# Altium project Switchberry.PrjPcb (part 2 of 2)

## Sheet 09-Switch_Power_Filters.SchDoc
size B; SheetNumber: 9; SheetTotal: 11
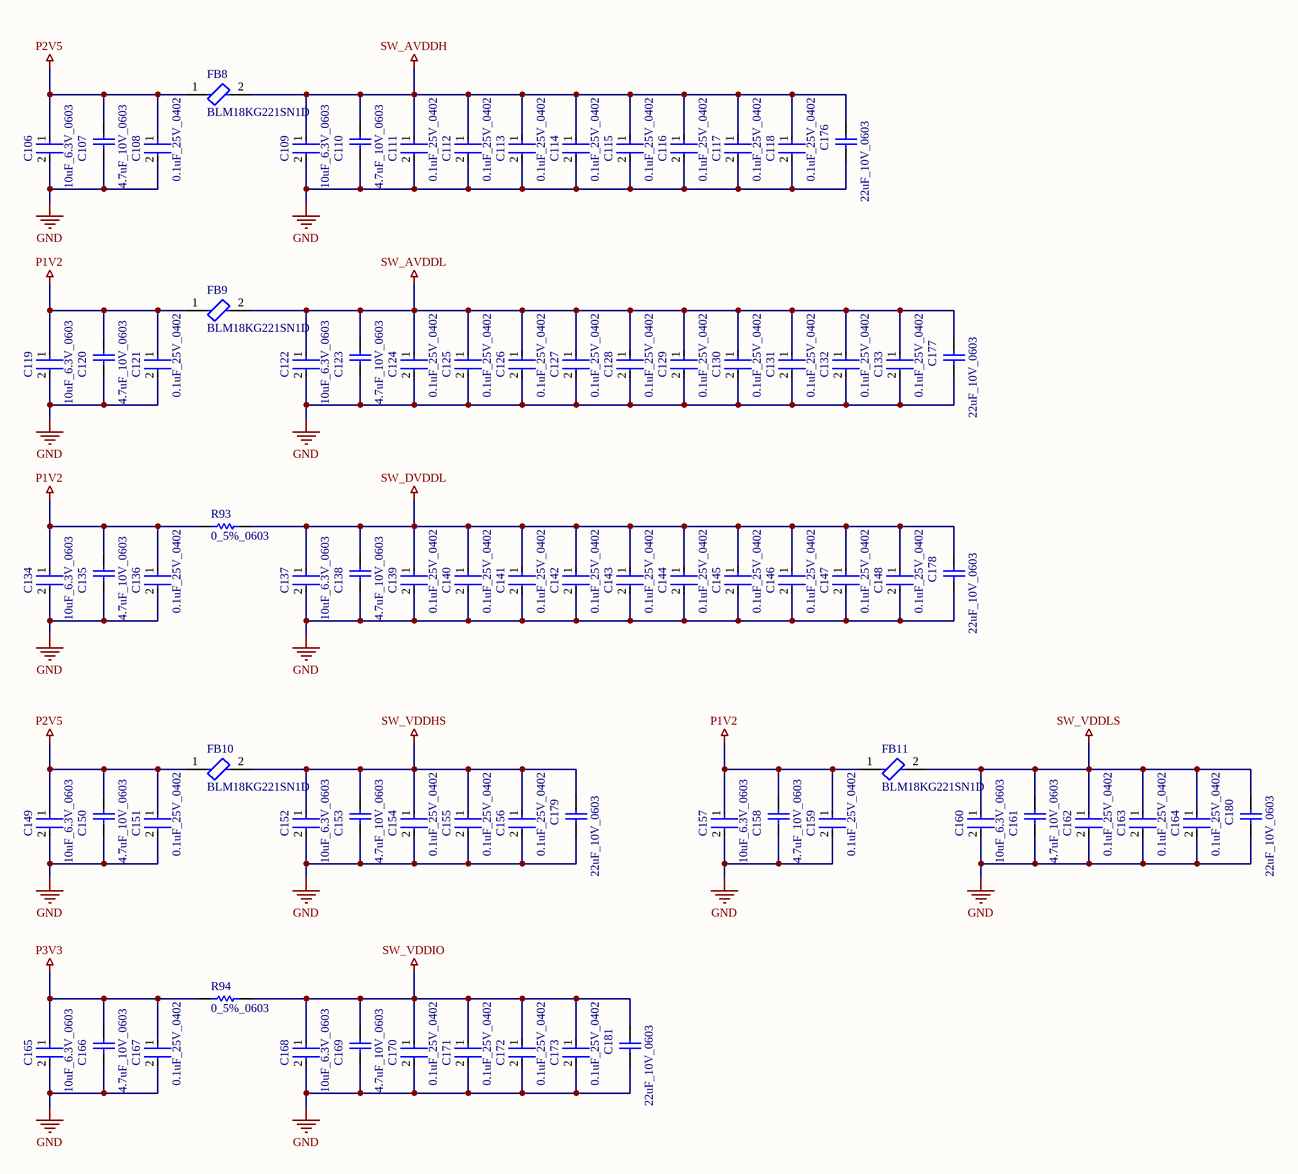
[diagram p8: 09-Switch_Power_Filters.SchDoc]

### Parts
C106  10uF_6.3V_0603  [FP-C0603C106M9PACTU-MFG]
C107  4.7uF_10V_0603  [CAPC1608X87X35NL15T15]
C108  0.1uF_25V_0402  [FP-0402-L_1_0_1-W_0_5_0_1-IPC_C]
C109  10uF_6.3V_0603  [FP-C0603C106M9PACTU-MFG]
C110  4.7uF_10V_0603  [CAPC1608X87X35NL15T15]
C111  0.1uF_25V_0402  [FP-0402-L_1_0_1-W_0_5_0_1-IPC_C]
C112  0.1uF_25V_0402  [FP-0402-L_1_0_1-W_0_5_0_1-IPC_C]
C113  0.1uF_25V_0402  [FP-0402-L_1_0_1-W_0_5_0_1-IPC_C]
C114  0.1uF_25V_0402  [FP-0402-L_1_0_1-W_0_5_0_1-IPC_C]
C115  0.1uF_25V_0402  [FP-0402-L_1_0_1-W_0_5_0_1-IPC_C]
C116  0.1uF_25V_0402  [FP-0402-L_1_0_1-W_0_5_0_1-IPC_C]
C117  0.1uF_25V_0402  [FP-0402-L_1_0_1-W_0_5_0_1-IPC_C]
C118  0.1uF_25V_0402  [FP-0402-L_1_0_1-W_0_5_0_1-IPC_C]
C119  10uF_6.3V_0603  [FP-C0603C106M9PACTU-MFG]
C120  4.7uF_10V_0603  [CAPC1608X87X35NL15T15]
C121  0.1uF_25V_0402  [FP-0402-L_1_0_1-W_0_5_0_1-IPC_C]
C122  10uF_6.3V_0603  [FP-C0603C106M9PACTU-MFG]
C123  4.7uF_10V_0603  [CAPC1608X87X35NL15T15]
C124  0.1uF_25V_0402  [FP-0402-L_1_0_1-W_0_5_0_1-IPC_C]
C125  0.1uF_25V_0402  [FP-0402-L_1_0_1-W_0_5_0_1-IPC_C]
C126  0.1uF_25V_0402  [FP-0402-L_1_0_1-W_0_5_0_1-IPC_C]
C127  0.1uF_25V_0402  [FP-0402-L_1_0_1-W_0_5_0_1-IPC_C]
C128  0.1uF_25V_0402  [FP-0402-L_1_0_1-W_0_5_0_1-IPC_C]
C129  0.1uF_25V_0402  [FP-0402-L_1_0_1-W_0_5_0_1-IPC_C]
C130  0.1uF_25V_0402  [FP-0402-L_1_0_1-W_0_5_0_1-IPC_C]
C131  0.1uF_25V_0402  [FP-0402-L_1_0_1-W_0_5_0_1-IPC_C]
C132  0.1uF_25V_0402  [FP-0402-L_1_0_1-W_0_5_0_1-IPC_C]
C133  0.1uF_25V_0402  [FP-0402-L_1_0_1-W_0_5_0_1-IPC_C]
C134  10uF_6.3V_0603  [FP-C0603C106M9PACTU-MFG]
C135  4.7uF_10V_0603  [CAPC1608X87X35NL15T15]
C136  0.1uF_25V_0402  [FP-0402-L_1_0_1-W_0_5_0_1-IPC_C]
C137  10uF_6.3V_0603  [FP-C0603C106M9PACTU-MFG]
C138  4.7uF_10V_0603  [CAPC1608X87X35NL15T15]
C139  0.1uF_25V_0402  [FP-0402-L_1_0_1-W_0_5_0_1-IPC_C]
C140  0.1uF_25V_0402  [FP-0402-L_1_0_1-W_0_5_0_1-IPC_C]
C141  0.1uF_25V_0402  [FP-0402-L_1_0_1-W_0_5_0_1-IPC_C]
C142  0.1uF_25V_0402  [FP-0402-L_1_0_1-W_0_5_0_1-IPC_C]
C143  0.1uF_25V_0402  [FP-0402-L_1_0_1-W_0_5_0_1-IPC_C]
C144  0.1uF_25V_0402  [FP-0402-L_1_0_1-W_0_5_0_1-IPC_C]
C145  0.1uF_25V_0402  [FP-0402-L_1_0_1-W_0_5_0_1-IPC_C]
C146  0.1uF_25V_0402  [FP-0402-L_1_0_1-W_0_5_0_1-IPC_C]
C147  0.1uF_25V_0402  [FP-0402-L_1_0_1-W_0_5_0_1-IPC_C]
C148  0.1uF_25V_0402  [FP-0402-L_1_0_1-W_0_5_0_1-IPC_C]
C149  10uF_6.3V_0603  [FP-C0603C106M9PACTU-MFG]
C150  4.7uF_10V_0603  [CAPC1608X87X35NL15T15]
C151  0.1uF_25V_0402  [FP-0402-L_1_0_1-W_0_5_0_1-IPC_C]
C152  10uF_6.3V_0603  [FP-C0603C106M9PACTU-MFG]
C153  4.7uF_10V_0603  [CAPC1608X87X35NL15T15]
C154  0.1uF_25V_0402  [FP-0402-L_1_0_1-W_0_5_0_1-IPC_C]
C155  0.1uF_25V_0402  [FP-0402-L_1_0_1-W_0_5_0_1-IPC_C]
C156  0.1uF_25V_0402  [FP-0402-L_1_0_1-W_0_5_0_1-IPC_C]
C157  10uF_6.3V_0603  [FP-C0603C106M9PACTU-MFG]
C158  4.7uF_10V_0603  [CAPC1608X87X35NL15T15]
C159  0.1uF_25V_0402  [FP-0402-L_1_0_1-W_0_5_0_1-IPC_C]
C160  10uF_6.3V_0603  [FP-C0603C106M9PACTU-MFG]
C161  4.7uF_10V_0603  [CAPC1608X87X35NL15T15]
C162  0.1uF_25V_0402  [FP-0402-L_1_0_1-W_0_5_0_1-IPC_C]
C163  0.1uF_25V_0402  [FP-0402-L_1_0_1-W_0_5_0_1-IPC_C]
C164  0.1uF_25V_0402  [FP-0402-L_1_0_1-W_0_5_0_1-IPC_C]
C165  10uF_6.3V_0603  [FP-C0603C106M9PACTU-MFG]
C166  4.7uF_10V_0603  [CAPC1608X87X35NL15T15]
C167  0.1uF_25V_0402  [FP-0402-L_1_0_1-W_0_5_0_1-IPC_C]
C168  10uF_6.3V_0603  [FP-C0603C106M9PACTU-MFG]
C169  4.7uF_10V_0603  [CAPC1608X87X35NL15T15]
C170  0.1uF_25V_0402  [FP-0402-L_1_0_1-W_0_5_0_1-IPC_C]
C171  0.1uF_25V_0402  [FP-0402-L_1_0_1-W_0_5_0_1-IPC_C]
C172  0.1uF_25V_0402  [FP-0402-L_1_0_1-W_0_5_0_1-IPC_C]
C173  0.1uF_25V_0402  [FP-0402-L_1_0_1-W_0_5_0_1-IPC_C]
C176  22uF_10V_0603  [CAPC1608X100X20ML10]
C177  22uF_10V_0603  [CAPC1608X100X20ML10]
C178  22uF_10V_0603  [CAPC1608X100X20ML10]
C179  22uF_10V_0603  [CAPC1608X100X20ML10]
C180  22uF_10V_0603  [CAPC1608X100X20ML10]
C181  22uF_10V_0603  [CAPC1608X100X20ML10]
FB8  BLM18KG221SN1D  [FP-BLM18-0_15-t0_8-IPC_B]
FB9  BLM18KG221SN1D  [FP-BLM18-0_15-t0_8-IPC_B]
FB10  BLM18KG221SN1D  [FP-BLM18-0_15-t0_8-IPC_B]
FB11  BLM18KG221SN1D  [FP-BLM18-0_15-t0_8-IPC_B]
R93  0_5%_0603  [RESC1608X55X25ML10T15]
R94  0_5%_0603  [RESC1608X55X25ML10T15]

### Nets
GND: C106.2 C107.1 C108.2 C109.2 C110.1 C111.2 C112.2 C113.2 C114.2 C115.2 C116.2 C117.2 C118.2 C119.2 C120.1 C121.2 C122.2 C123.1 C124.2 C125.2 C126.2 C127.2 C128.2 C129.2 C130.2 C131.2 C132.2 C133.2 C134.2 C135.1 C136.2 C137.2 C138.1 C139.2 C140.2 C141.2 C142.2 C143.2 C144.2 C145.2 C146.2 C147.2 C148.2 C149.2 C150.1 C151.2 C152.2 C153.1 C154.2 C155.2 C156.2 C157.2 C158.1 C159.2 C160.2 C161.1 C162.2 C163.2 C164.2 C165.2 C166.1 C167.2 C168.2 C169.1 C170.2 C171.2 C172.2 C173.2 C176.1 C177.1 C178.1 C179.1 C180.1 C181.1
P1V2: C119.1 C120.2 C121.1 C134.1 C135.2 C136.1 C157.1 C158.2 C159.1 FB9.1 FB11.1 R93.1
P2V5: C106.1 C107.2 C108.1 C149.1 C150.2 C151.1 FB8.1 FB10.1
P3V3: C165.1 C166.2 C167.1 R94.1
SW_AVDDH: C109.1 C110.2 C111.1 C112.1 C113.1 C114.1 C115.1 C116.1 C117.1 C118.1 C176.2 FB8.2
SW_AVDDL: C122.1 C123.2 C124.1 C125.1 C126.1 C127.1 C128.1 C129.1 C130.1 C131.1 C132.1 C133.1 C177.2 FB9.2
SW_DVDDL: C137.1 C138.2 C139.1 C140.1 C141.1 C142.1 C143.1 C144.1 C145.1 C146.1 C147.1 C148.1 C178.2 R93.2
SW_VDDHS: C152.1 C153.2 C154.1 C155.1 C156.1 C179.2 FB10.2
SW_VDDIO: C168.1 C169.2 C170.1 C171.1 C172.1 C173.1 C181.2 R94.2
SW_VDDLS: C160.1 C161.2 C162.1 C163.1 C164.1 C180.2 FB11.2

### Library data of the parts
C106 C109 C119 C122 C134 C137 C149 C152 C157 C160 C165 C168 = CMP-2006-02285-3: CAP CER 10UF 6.3V X5R 0603; Manufacturer Part Number: C0603C106M9PACTU; Manufacturer: Kemet; Material: Ceramic; Temperature Coefficient: 15%; Tolerance: 20%
C107 C110 C120 C123 C135 C138 C150 C153 C158 C161 C166 C169 = CMP-2006-03238-1: Part Number: C0603C475K8PACTU; Manufacturer: Kemet
C108 C111-C118 C121 C124-C133 C136 C139-C148 C151 C154-C156 C159 C162-C164 C167 C170-C173 = CMP-2008-02519-2: General Purpose Ceramic Capacitor, 0402, 100nF, 10%, X7R, 15%, 25V
C176-C181 = CMP-2000-05441-1: Chip Capacitor, 22 uF, +/- 20%, 10 V, -55 to 85 degC, 0603 (1608 Metric), RoHS, Tape and Reel; Manufacturer: TDK; PCN Part Number: MLCCPartNumberChange30/Nov/2012; Voltage - Rated: 10V; Product Training Modules: CSeriesGeneralApplicationsSEAT,CCV,andTVCLDesignToolsGuidetoReplacinganElectrolyticCapacitorwithanMLCC; Other Names: 445-9077-1; Design Resources: 20WNon-IsolatedBuckLEDDriverUsingPLLNK460KG; Online Catalog: CSeries,GeneralPurpose; Capacitance: 22µF; Temperature Coefficient: X5R; Kits: 445-9014-KIT-ND-KITMLCC100PF-22UF060310-50V
FB8-FB11 = CMP-0686-00556-7: Chip Ferrite Bead, 0603, 220Ω @ 100MHz, 0.05Ω, 25%, 2.2A; DC Resistance (DCR): 50mR; Number of Circuits: 1; Impedance: 220R
R93 R94 = CMP-2100-03667-1: Chip Resistor, 0 Ohm, +/- 5%, 0.1 W, -55 to 155 degC, 0603 (1608 Metric), RoHS, Tape and Reel; Manufacturer: Yageo; Temperature Coefficient: 200ppm/degreesC; Voltage Rating: 50V; Power Rating: 100mW; Resistance: 0mOhm

## Sheet 10-RJ45_Protection.SchDoc
size B; SheetNumber: 10; SheetTotal: 13
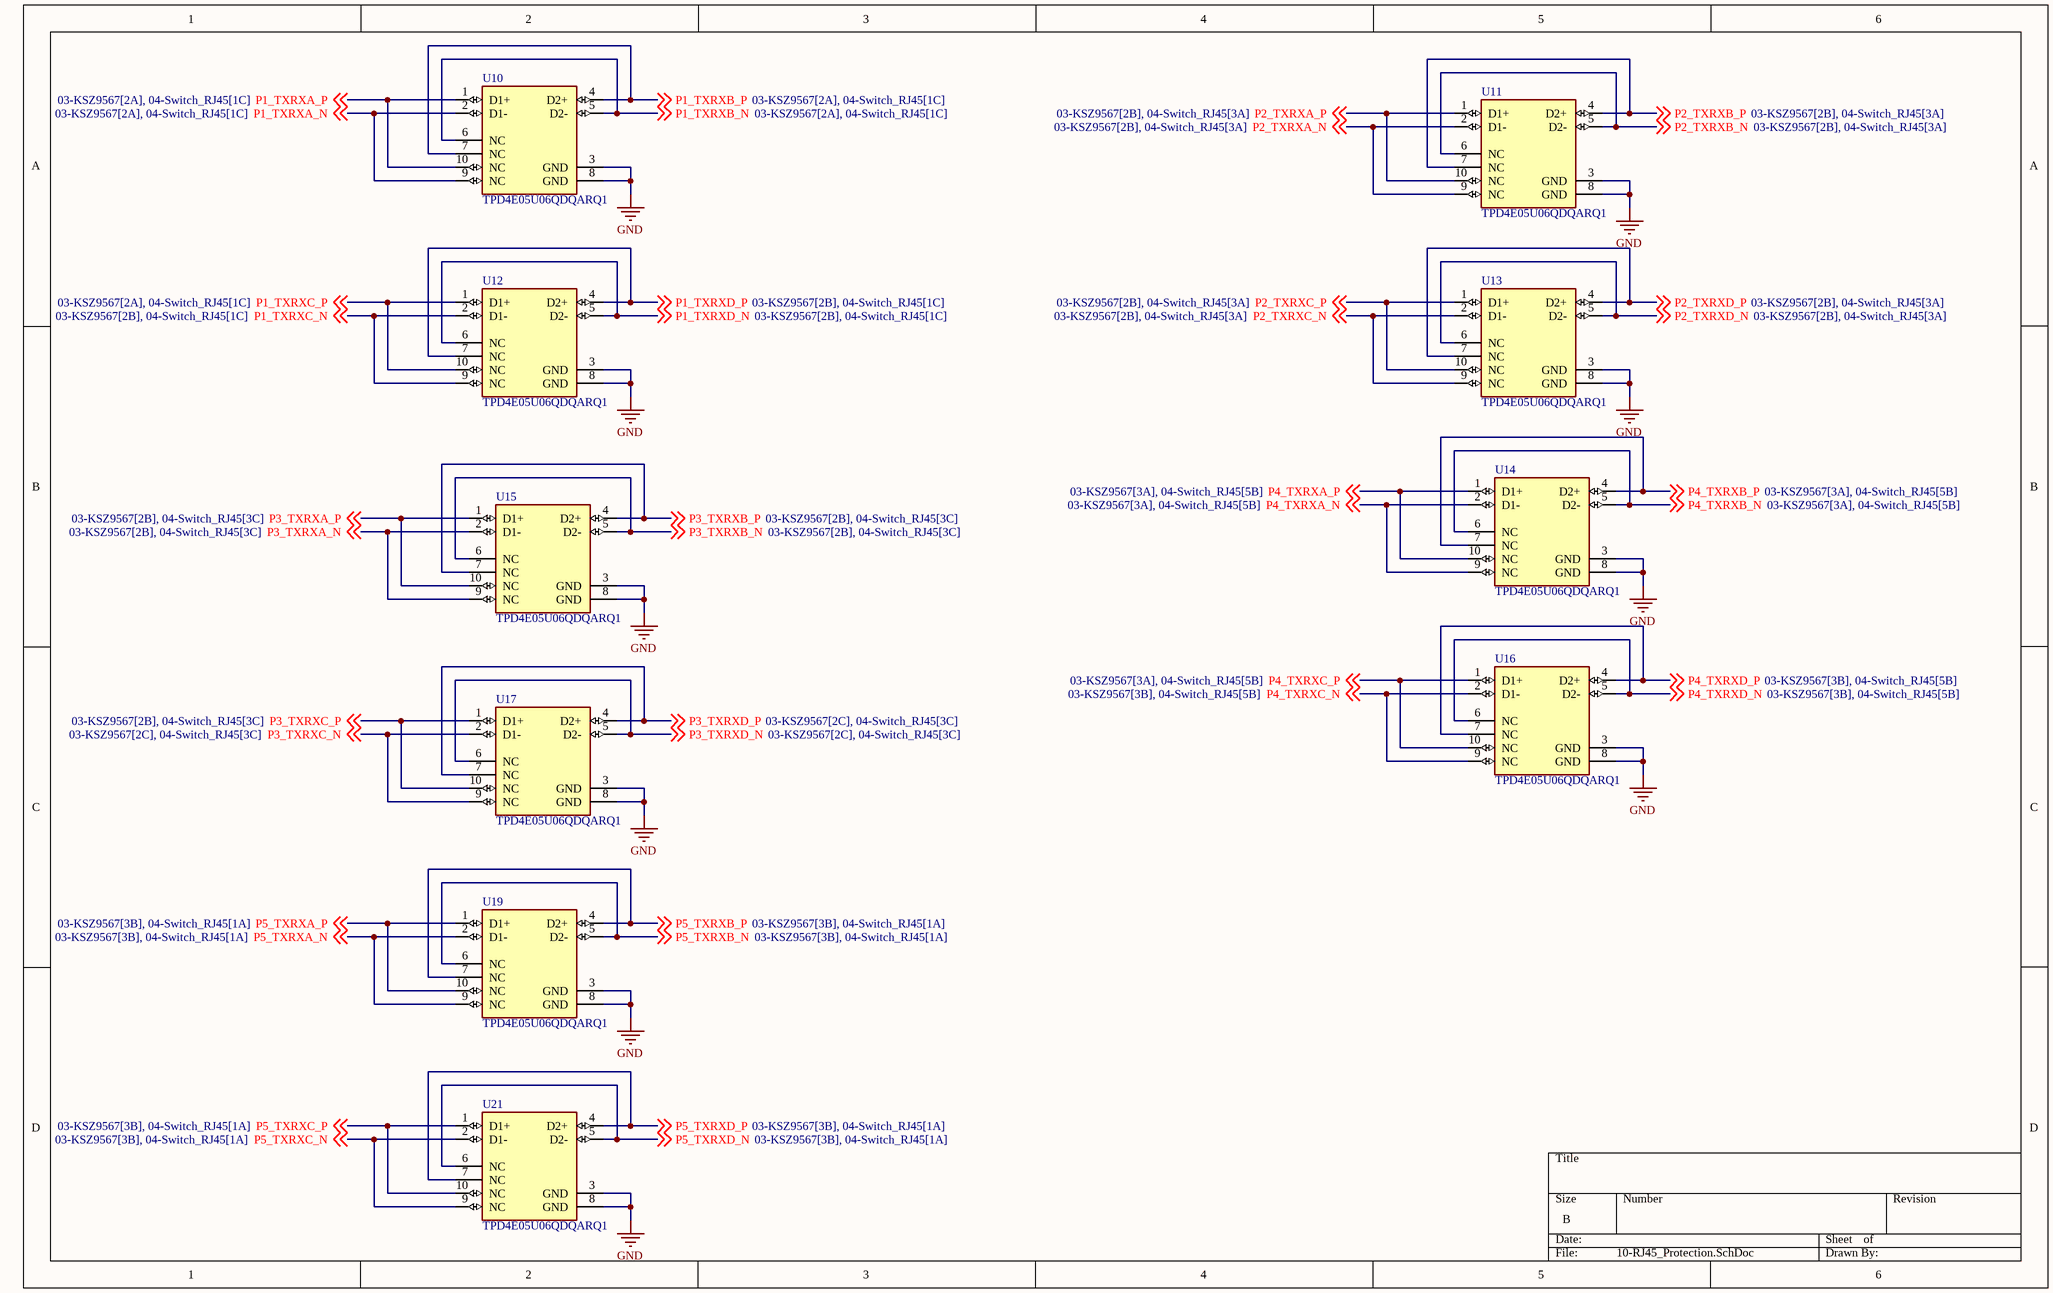
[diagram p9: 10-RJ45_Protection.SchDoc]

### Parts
U10  TPD4E05U06QDQARQ1  [FP-DQA0010A-MFG]
U11  TPD4E05U06QDQARQ1  [FP-DQA0010A-MFG]
U12  TPD4E05U06QDQARQ1  [FP-DQA0010A-MFG]
U13  TPD4E05U06QDQARQ1  [FP-DQA0010A-MFG]
U14  TPD4E05U06QDQARQ1  [FP-DQA0010A-MFG]
U15  TPD4E05U06QDQARQ1  [FP-DQA0010A-MFG]
U16  TPD4E05U06QDQARQ1  [FP-DQA0010A-MFG]
U17  TPD4E05U06QDQARQ1  [FP-DQA0010A-MFG]
U19  TPD4E05U06QDQARQ1  [FP-DQA0010A-MFG]
U21  TPD4E05U06QDQARQ1  [FP-DQA0010A-MFG]

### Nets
GND: U10.3(GND) U10.8(GND) U11.3(GND) U11.8(GND) U12.3(GND) U12.8(GND) U13.3(GND) U13.8(GND) U14.3(GND) U14.8(GND) U15.3(GND) U15.8(GND) U16.3(GND) U16.8(GND) U17.3(GND) U17.8(GND) U19.3(GND) U19.8(GND) U21.3(GND) U21.8(GND)
P1_TXRXA_N: U10.2(D1-) U10.9(NC) ; off-sheet P1_TXRXA_N
P1_TXRXA_P: U10.1(D1+) U10.10(NC) ; off-sheet P1_TXRXA_P
P1_TXRXB_N: U10.5(D2-) U10.6(NC) ; off-sheet P1_TXRXB_N
P1_TXRXB_P: U10.4(D2+) U10.7(NC) ; off-sheet P1_TXRXB_P
P1_TXRXC_N: U12.2(D1-) U12.9(NC) ; off-sheet P1_TXRXC_N
P1_TXRXC_P: U12.1(D1+) U12.10(NC) ; off-sheet P1_TXRXC_P
P1_TXRXD_N: U12.5(D2-) U12.6(NC) ; off-sheet P1_TXRXD_N
P1_TXRXD_P: U12.4(D2+) U12.7(NC) ; off-sheet P1_TXRXD_P
P2_TXRXA_N: U11.2(D1-) U11.9(NC) ; off-sheet P2_TXRXA_N
P2_TXRXA_P: U11.1(D1+) U11.10(NC) ; off-sheet P2_TXRXA_P
P2_TXRXB_N: U11.5(D2-) U11.6(NC) ; off-sheet P2_TXRXB_N
P2_TXRXB_P: U11.4(D2+) U11.7(NC) ; off-sheet P2_TXRXB_P
P2_TXRXC_N: U13.2(D1-) U13.9(NC) ; off-sheet P2_TXRXC_N
P2_TXRXC_P: U13.1(D1+) U13.10(NC) ; off-sheet P2_TXRXC_P
P2_TXRXD_N: U13.5(D2-) U13.6(NC) ; off-sheet P2_TXRXD_N
P2_TXRXD_P: U13.4(D2+) U13.7(NC) ; off-sheet P2_TXRXD_P
P3_TXRXA_N: U15.2(D1-) U15.9(NC) ; off-sheet P3_TXRXA_N
P3_TXRXA_P: U15.1(D1+) U15.10(NC) ; off-sheet P3_TXRXA_P
P3_TXRXB_N: U15.5(D2-) U15.6(NC) ; off-sheet P3_TXRXB_N
P3_TXRXB_P: U15.4(D2+) U15.7(NC) ; off-sheet P3_TXRXB_P
P3_TXRXC_N: U17.2(D1-) U17.9(NC) ; off-sheet P3_TXRXC_N
P3_TXRXC_P: U17.1(D1+) U17.10(NC) ; off-sheet P3_TXRXC_P
P3_TXRXD_N: U17.5(D2-) U17.6(NC) ; off-sheet P3_TXRXD_N
P3_TXRXD_P: U17.4(D2+) U17.7(NC) ; off-sheet P3_TXRXD_P
P4_TXRXA_N: U14.2(D1-) U14.9(NC) ; off-sheet P4_TXRXA_N
P4_TXRXA_P: U14.1(D1+) U14.10(NC) ; off-sheet P4_TXRXA_P
P4_TXRXB_N: U14.5(D2-) U14.6(NC) ; off-sheet P4_TXRXB_N
P4_TXRXB_P: U14.4(D2+) U14.7(NC) ; off-sheet P4_TXRXB_P
P4_TXRXC_N: U16.2(D1-) U16.9(NC) ; off-sheet P4_TXRXC_N
P4_TXRXC_P: U16.1(D1+) U16.10(NC) ; off-sheet P4_TXRXC_P
P4_TXRXD_N: U16.5(D2-) U16.6(NC) ; off-sheet P4_TXRXD_N
P4_TXRXD_P: U16.4(D2+) U16.7(NC) ; off-sheet P4_TXRXD_P
P5_TXRXA_N: U19.2(D1-) U19.9(NC) ; off-sheet P5_TXRXA_N
P5_TXRXA_P: U19.1(D1+) U19.10(NC) ; off-sheet P5_TXRXA_P
P5_TXRXB_N: U19.5(D2-) U19.6(NC) ; off-sheet P5_TXRXB_N
P5_TXRXB_P: U19.4(D2+) U19.7(NC) ; off-sheet P5_TXRXB_P
P5_TXRXC_N: U21.2(D1-) U21.9(NC) ; off-sheet P5_TXRXC_N
P5_TXRXC_P: U21.1(D1+) U21.10(NC) ; off-sheet P5_TXRXC_P
P5_TXRXD_N: U21.5(D2-) U21.6(NC) ; off-sheet P5_TXRXD_N
P5_TXRXD_P: U21.4(D2+) U21.7(NC) ; off-sheet P5_TXRXD_P

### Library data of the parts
U10-U17 U19 U21 = CMP-04985-000004-1: TVS DIODE 5.5V 14V 10USON; Manufacturer: Texas Instruments; Direction: Unidirectional; Standoff Height: 0mm; Capacitance: 0.5pF; Number Of Channels: 4; Breakdown Voltage: 6.4V; Peak Pulse Power: 2.5W; Automotive Grade: Grade 1; Value: 0.5pF; Interface: USB,Ethernet,LVDS,Other; Peak Pulse Current: 2.5A

## Sheet 11-Switch_Strapping.SchDoc
size A; SheetNumber: 11; SheetTotal: 11
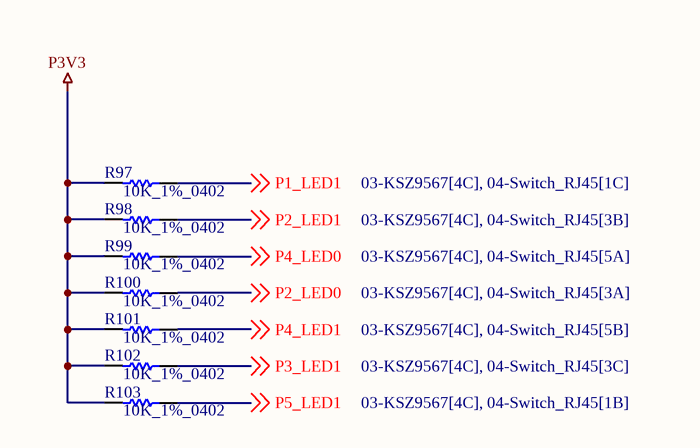
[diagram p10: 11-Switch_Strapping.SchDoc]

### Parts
R97  10K_1%_0402  [RESC1005X40X25NL10T10]
R98  10K_1%_0402  [RESC1005X40X25NL10T10]
R99  10K_1%_0402  [RESC1005X40X25NL10T10]
R100  10K_1%_0402  [RESC1005X40X25NL10T10]
R101  10K_1%_0402  [RESC1005X40X25NL10T10]
R102  10K_1%_0402  [RESC1005X40X25NL10T10]
R103  10K_1%_0402  [RESC1005X40X25NL10T10]

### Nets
P3V3: R97.2 R98.2 R99.2 R100.2 R101.2 R102.2 R103.2
P1_LED1: R97.1 ; off-sheet P1_LED1
P2_LED0: R100.1 ; off-sheet P2_LED0
P2_LED1: R98.1 ; off-sheet P2_LED1
P3_LED1: R102.1 ; off-sheet P3_LED1
P4_LED0: R99.1 ; off-sheet P4_LED0
P4_LED1: R101.1 ; off-sheet P4_LED1
P5_LED1: R103.1 ; off-sheet P5_LED1

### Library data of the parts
R97-R103 = CMP-2002-04694-1: Manufacturer: Bourns; Part Number: CR0402-FX-1002GLF

## Sheet 12-I225_1.SchDoc
size C; SheetNumber: 12; SheetTotal: 13
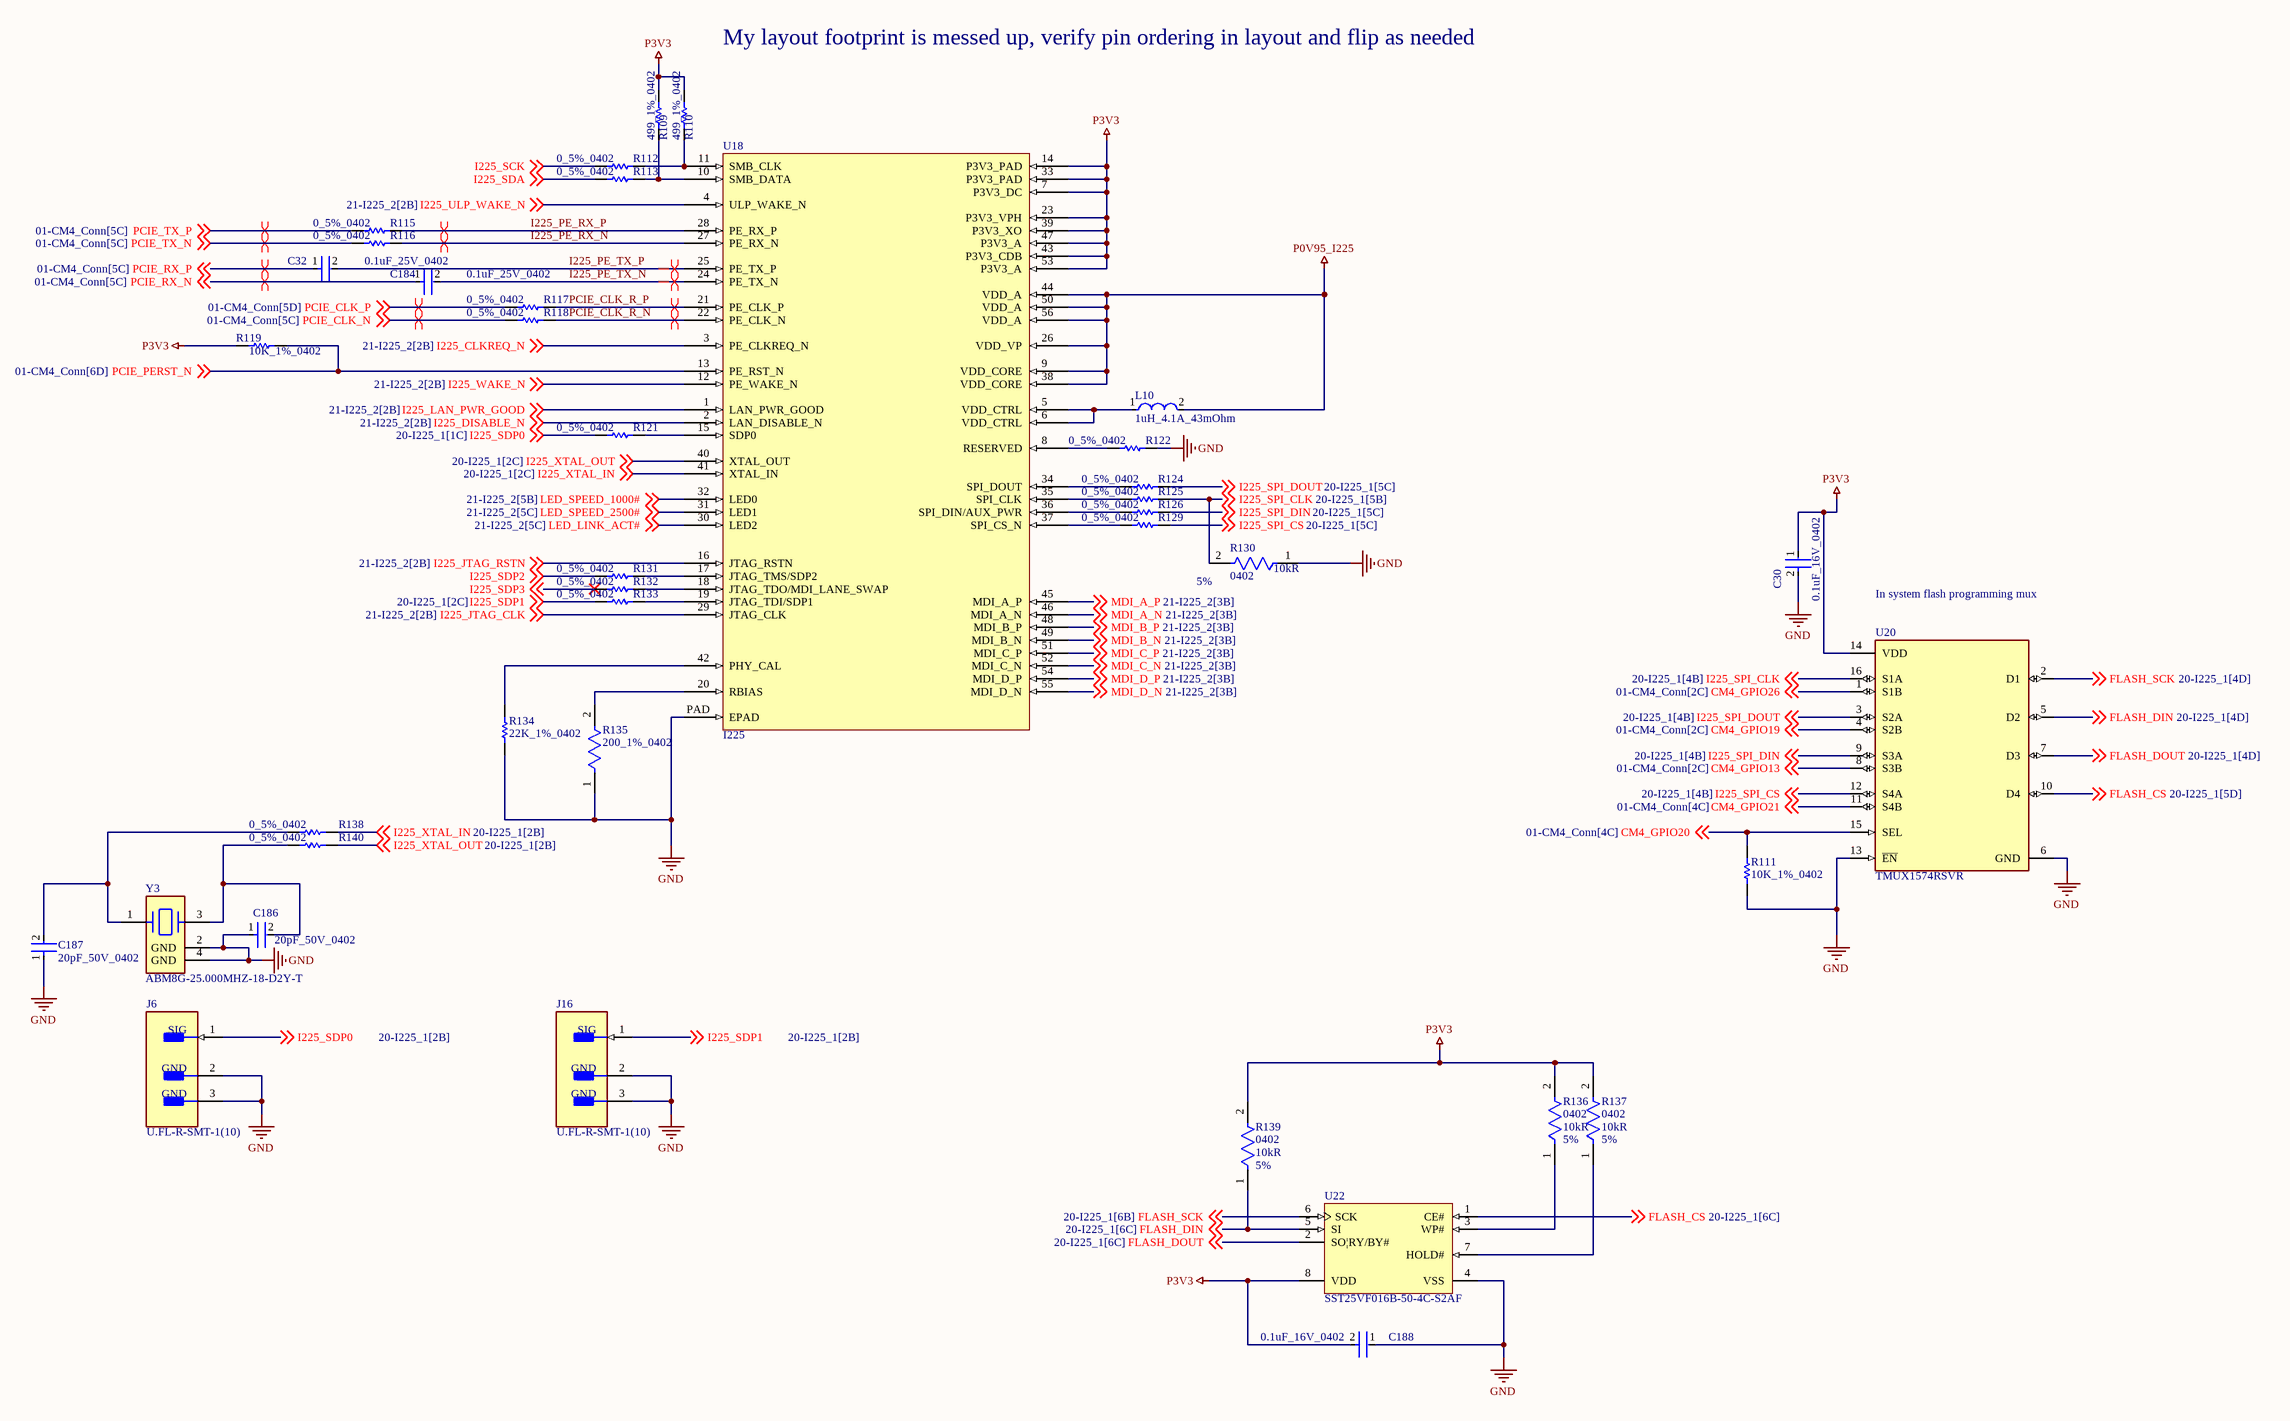
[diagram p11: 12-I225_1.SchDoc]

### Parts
C30  0.1uF_16V_0402  [FP-GRM15-MFG]
C32  0.1uF_25V_0402  [FP-0402-L_1_0_1-W_0_5_0_1-IPC_C]
C184  0.1uF_25V_0402  [FP-0402-L_1_0_1-W_0_5_0_1-IPC_C]
C186  20pF_50V_0402  [FP-C0402-BB-MFG]
C187  20pF_50V_0402  [FP-C0402-BB-MFG]
C188  0.1uF_16V_0402  [FP-GRM15-MFG]
J6  U.FL-R-SMT-1(10)  [FP-U_FL-R-SMT-1_10-MFG]
J16  U.FL-R-SMT-1(10)  [FP-U_FL-R-SMT-1_10-MFG]
L10  1uH_4.1A_43mOhm  [FP-CIGT201610-MFG]
R109  499_1%_0402  [RESC1005X40X25LL05T05]
R110  499_1%_0402  [RESC1005X40X25LL05T05]
R111  10K_1%_0402  [RESC1005X40X25NL10T10]
R112  0_5%_0402  [RESC1005X40X25LL10T10]
R113  0_5%_0402  [RESC1005X40X25LL10T10]
R115  0_5%_0402  [RESC1005X40X25LL10T10]
R116  0_5%_0402  [RESC1005X40X25LL10T10]
R117  0_5%_0402  [RESC1005X40X25LL10T10]
R118  0_5%_0402  [RESC1005X40X25LL10T10]
R119  10K_1%_0402  [RESC1005X40X25NL10T10]
R121  0_5%_0402  [RESC1005X40X25LL10T10]
R122  0_5%_0402  [RESC1005X40X25LL10T10]
R124  0_5%_0402  [RESC1005X40X25LL10T10]
R125  0_5%_0402  [RESC1005X40X25LL10T10]
R126  0_5%_0402  [RESC1005X40X25LL10T10]
R129  0_5%_0402  [RESC1005X40X25LL10T10]
R130  Case/Package: 0402  Resistance: 10kR  Tolerance: 5%  [FP-CRCW0402-e3-IPC_B]  (hidden comment: CRCW040210K0JNED)
R131  0_5%_0402  [RESC1005X40X25LL10T10]
R132  0_5%_0402  [RESC1005X40X25LL10T10]
R133  0_5%_0402  [RESC1005X40X25LL10T10]
R134  22K_1%_0402  [RESC1005X40X25NL05T05]
R135  200_1%_0402  [FP-CRCW0402-e3-IPC_C]
R136  Case/Package: 0402  Resistance: 10kR  Tolerance: 5%  [FP-CRCW0402-e3-IPC_B]  (hidden comment: CRCW040210K0JNED)
R137  Case/Package: 0402  Resistance: 10kR  Tolerance: 5%  [FP-CRCW0402-e3-IPC_B]  (hidden comment: CRCW040210K0JNED)
R138  0_5%_0402  [RESC1005X40X25LL10T10]
R139  Case/Package: 0402  Resistance: 10kR  Tolerance: 5%  [FP-CRCW0402-e3-IPC_B]  (hidden comment: CRCW040210K0JNED)
R140  0_5%_0402  [RESC1005X40X25LL10T10]
U18  I225  [I225 QFN56]
U20  TMUX1574RSVR  [FP-RSV0016A-MFG]
U22  SST25VF016B-50-4C-S2AF  [MCHP-SOIC-S2A8_M]
Y3  ABM8G-25.000MHZ-18-D2Y-T  [FP-ABM8G-MFG]

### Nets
GND: C30.2 C186.1 C187.1 C188.1 J6.2(GND) J6.3(GND) J16.2(GND) J16.3(GND) R111.2 R122.2 R130.1 R134.1 R135.1 U18.PAD(EPAD) U20.6(GND) U20.13(~{EN}) U22.4(VSS) Y3.2(GND) Y3.4(GND)
P0V95_I225: L10.2 U18.9(VDD_CORE) U18.26(VDD_VP) U18.38(VDD_CORE) U18.44(VDD_A) U18.50(VDD_A) U18.56(VDD_A)
P3V3: C30.1 C188.2 R109.2 R110.2 R119.2 R136.2 R137.2 R139.2 U18.7(P3V3_DC) U18.14(P3V3_PAD) U18.23(P3V3_VPH) U18.33(P3V3_PAD) U18.39(P3V3_XO) U18.43(P3V3_CDB) U18.47(P3V3_A) U18.53(P3V3_A) U20.14(VDD) U22.8(VDD)
CM4_GPIO13: U20.8(S3B) ; off-sheet CM4_GPIO13
CM4_GPIO19: U20.4(S2B) ; off-sheet CM4_GPIO19
CM4_GPIO20: R111.1 U20.15(SEL) ; off-sheet CM4_GPIO20
CM4_GPIO21: U20.11(S4B) ; off-sheet CM4_GPIO21
CM4_GPIO26: U20.1(S1B) ; off-sheet CM4_GPIO26
FLASH_CS: U20.10(D4) U22.1(CE#) ; off-sheet FLASH_CS
FLASH_DIN: R139.1 U20.5(D2) U22.5(SI) ; off-sheet FLASH_DIN
FLASH_DOUT: U20.7(D3) U22.2(SO¦RY/BY#) ; off-sheet FLASH_DOUT
FLASH_SCK: U20.2(D1) U22.6(SCK) ; off-sheet FLASH_SCK
I225_CLKREQ_N: U18.3(PE_CLKREQ_N) ; off-sheet I225_CLKREQ_N
I225_DISABLE_N: U18.2(LAN_DISABLE_N) ; off-sheet I225_DISABLE_N
I225_JTAG_CLK: U18.29(JTAG_CLK) ; off-sheet I225_JTAG_CLK
I225_JTAG_RSTN: U18.16(JTAG_RSTN) ; off-sheet I225_JTAG_RSTN
I225_LAN_PWR_GOOD: U18.1(LAN_PWR_GOOD) ; off-sheet I225_LAN_PWR_GOOD
I225_PE_RX_N: R116.2 U18.27(PE_RX_N)
I225_PE_RX_P: R115.2 U18.28(PE_RX_P)
I225_PE_TX_N: C184.2 U18.24(PE_TX_N)
I225_PE_TX_P: C32.2 U18.25(PE_TX_P)
I225_SCK: R112.1 ; off-sheet I225_SCK
I225_SDA: R113.1 ; off-sheet I225_SDA
I225_SDP0: J6.1(SIG) R121.1 ; off-sheet I225_SDP0
I225_SDP1: J16.1(SIG) R133.1 ; off-sheet I225_SDP1
I225_SDP2: R131.1 ; off-sheet I225_SDP2
I225_SDP3: R132.1 ; off-sheet I225_SDP3
I225_SPI_CLK: R125.2 R130.2 U20.16(S1A) ; off-sheet I225_SPI_CLK
I225_SPI_CS: R129.2 U20.12(S4A) ; off-sheet I225_SPI_CS
I225_SPI_DIN: R126.2 U20.9(S3A) ; off-sheet I225_SPI_DIN
I225_SPI_DOUT: R124.2 U20.3(S2A) ; off-sheet I225_SPI_DOUT
I225_ULP_WAKE_N: U18.4(ULP_WAKE_N) ; off-sheet I225_ULP_WAKE_N
I225_WAKE_N: U18.12(PE_WAKE_N) ; off-sheet I225_WAKE_N
I225_XTAL_IN: R138.2 U18.41(XTAL_IN) ; off-sheet I225_XTAL_IN
I225_XTAL_OUT: R140.2 U18.40(XTAL_OUT) ; off-sheet I225_XTAL_OUT
LED_LINK_ACT#: U18.30(LED2) ; off-sheet LED_LINK_ACT#
LED_SPEED_1000#: U18.32(LED0) ; off-sheet LED_SPEED_1000#
LED_SPEED_2500#: U18.31(LED1) ; off-sheet LED_SPEED_2500#
MDI_A_N: U18.46(MDI_A_N) ; off-sheet MDI_A_N
MDI_A_P: U18.45(MDI_A_P) ; off-sheet MDI_A_P
MDI_B_N: U18.49(MDI_B_N) ; off-sheet MDI_B_N
MDI_B_P: U18.48(MDI_B_P) ; off-sheet MDI_B_P
MDI_C_N: U18.52(MDI_C_N) ; off-sheet MDI_C_N
MDI_C_P: U18.51(MDI_C_P) ; off-sheet MDI_C_P
MDI_D_N: U18.55(MDI_D_N) ; off-sheet MDI_D_N
MDI_D_P: U18.54(MDI_D_P) ; off-sheet MDI_D_P
PCIE_CLK_N: R118.1 ; off-sheet PCIE_CLK_N
PCIE_CLK_P: R117.1 ; off-sheet PCIE_CLK_P
PCIE_CLK_R_N: R118.2 U18.22(PE_CLK_N)
PCIE_CLK_R_P: R117.2 U18.21(PE_CLK_P)
PCIE_PERST_N: R119.1 U18.13(PE_RST_N) ; off-sheet PCIE_PERST_N
PCIE_RX_N: C184.1 ; off-sheet PCIE_RX_N
PCIE_RX_P: C32.1 ; off-sheet PCIE_RX_P
PCIE_TX_N: R116.1 ; off-sheet PCIE_TX_N
PCIE_TX_P: R115.1 ; off-sheet PCIE_TX_P
NetC186_2: C186.2 R140.1 Y3.3
NetC187_2: C187.2 R138.1 Y3.1
NetL10_1: L10.1 U18.5(VDD_CTRL) U18.6(VDD_CTRL)
NetR109_1: R109.1 R113.2 U18.10(SMB_DATA)
NetR110_1: R110.1 R112.2 U18.11(SMB_CLK)
NetR121_2: R121.2 U18.15(SDP0)
NetR122_1: R122.1 U18.8(RESERVED)
NetR124_1: R124.1 U18.34(SPI_DOUT)
NetR125_1: R125.1 U18.35(SPI_CLK)
NetR126_1: R126.1 U18.36(SPI_DIN/AUX_PWR)
NetR129_1: R129.1 U18.37(SPI_CS_N)
NetR131_2: R131.2 U18.17(JTAG_TMS/SDP2)
NetR132_2: R132.2 U18.18(JTAG_TDO/MDI_LANE_SWAP)
NetR133_2: R133.2 U18.19(JTAG_TDI/SDP1)
NetR134_2: R134.2 U18.42(PHY_CAL)
NetR135_2: R135.2 U18.20(RBIAS)
NetR136_1: R136.1 U22.3(WP#)
NetR137_1: R137.1 U22.7(HOLD#)

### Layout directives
differential pair: I225_PE_RX_N, I225_PE_RX_P, I225_PE_TX_N, I225_PE_TX_P, PCIE_CLK_N, PCIE_CLK_P, PCIE_CLK_R_N, PCIE_CLK_R_P, PCIE_RX_N, PCIE_RX_P, PCIE_TX_N, PCIE_TX_P

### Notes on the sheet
- My layout footprint is messed up, verify pin ordering in layout and flip as needed
- In system flash programming mux

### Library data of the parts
C30 C188 = CMP-2100-03641-2: CAP CER 0.1UF 16V X7R 0402; Manufacturer Part Number: GRM155R71C104KA88D; Manufacturer: Murata; Standoff Height: 0mm; Tolerance: 10%; Voltage Rating: 16Vdc; Material: Ceramic; Capacitance: 0.10μF; Value: 0.10μF
C32 C184 = CMP-2008-02519-2: as C108 on sheet 09-Switch_Power_Filters
C186 C187 = CMP-1034-00890-3: CAP CER 20PF 50V 5% NP0 0402; Manufacturer Part Number: C0402C200J5GACTU; Manufacturer: Kemet; Tolerance: 0.05; Material: Ceramic; Temperature Characteristic: C0G; Temperature Coefficient: 15%
J6 J16 = CMP-2000-05152-3: CONN U.FL RCPT STR 50 OHM SMD; Max Frequency: 6GHz; Connector Type: Coaxial; Body Plating: Silver; Body Material: Bronze; Impedance: 50R; Dielectric Material: Polymer; Insulation Resistance: 500MR; Gender: Male
L10 = CMP-13278-000005-1: FIXED IND 1UH 4.1A 43 MOHM SMD; DC Resistance (DCR): 43mR; Shielding: Unshielded; Saturation Current: 4.5A; Tolerance: 20%; Core Material: Metal; Test Frequency: 1MHz
R109 R110 = CMP-2002-00965-1: Manufacturer: Panasonic; Part Number: ERJ-2RKF4990X
R111 R119 = CMP-2002-04694-1: as R97-R103 on sheet 11-Switch_Strapping
R112 R113 R115-R118 R121 R122 R124-R126 R129 R131-R133 R138 R140 = CMP-2002-04569-1: Manufacturer: KOA Speer; Part Number: RK73Z1ETTP
R130 R136 R137 R139 = CMP-2002-08136-3: RES Thick Film, 10kΩ, 5%, 0.063W, 200ppm/°C, 0402; Voltage Rating: 50V; Power Rating: 63mW
R134 = CMP-1011-00659-2: Part Number: CRCW040222K0FKED; Manufacturer: Vishay Dale
R135 = CMP-1011-00429-3: RES Thick Film, 200Ω, 1%, 0.063W, 100ppm/°C, 0402; Max Power Dissipation: 63mW; Voltage Rating: 50V; Resistance: 200R
U20 = CMP-04892-000064-2: IC SWITCH SPDT QUAD 16UQFN
U22 = CMP-0378-00041-1: 16 Mbit SPI Serial Flash, 2.7 to 3.6 V, 50 MHz, 0 to 70 degC, 8-pin SOIC (S2A8), Tube; Manufacturer: Microchip
Y3 = CMP-2000-05733-2: CRYSTAL 25.0000MHZ 18PF SMD; Manufacturer: Abracon; Stability: 30ppm; Frequency: 25MHz; Esr: 60Ω; Tolerance: 20ppm

## Sheet 13-I225_2.SchDoc
size B; SheetNumber: 13; SheetTotal: 13
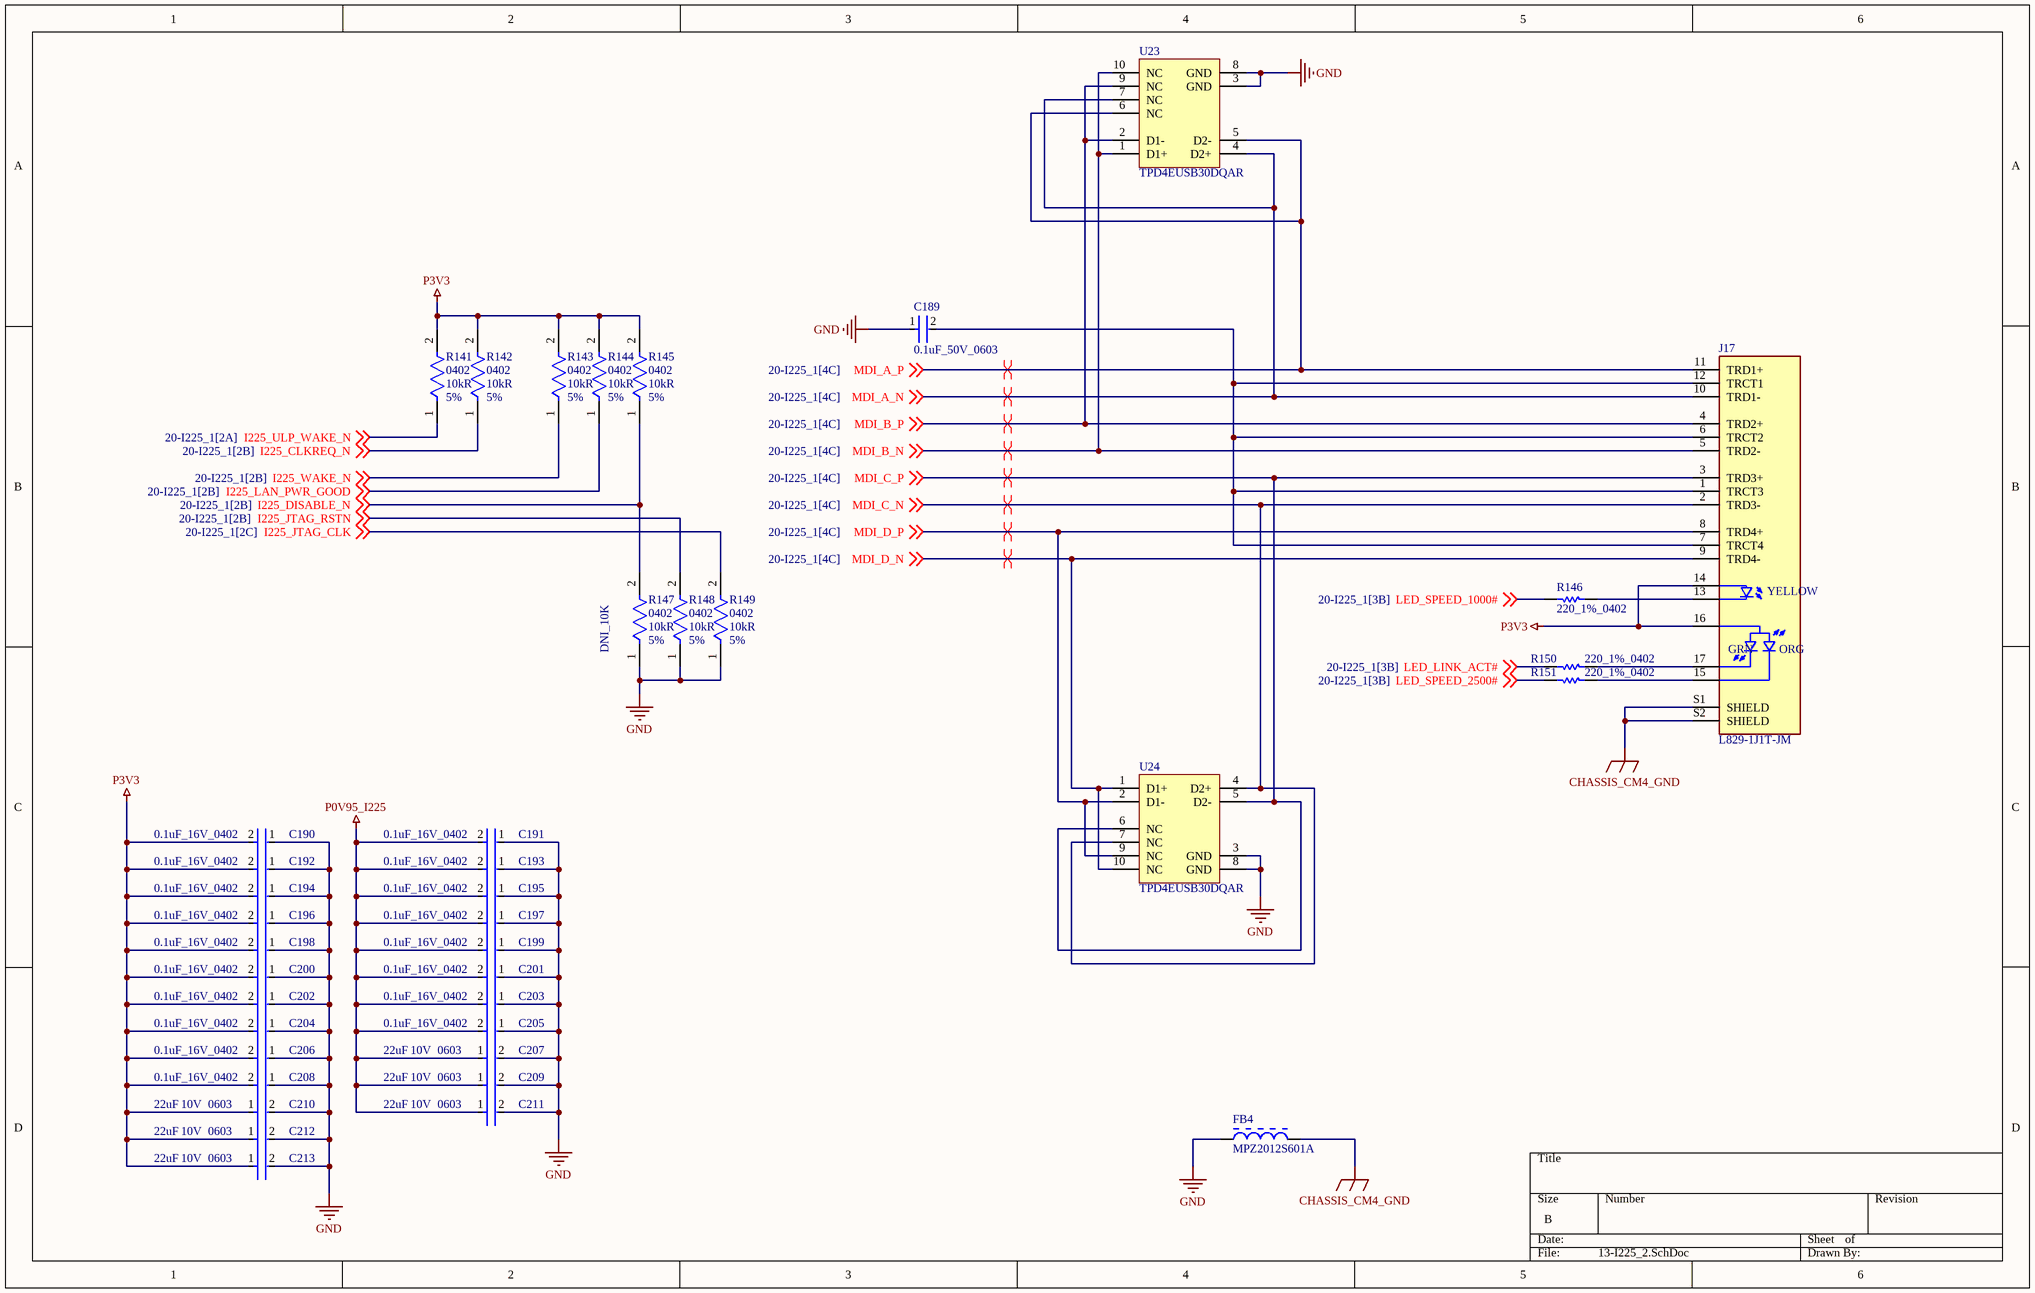
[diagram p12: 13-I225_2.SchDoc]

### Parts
C189  0.1uF_50V_0603  [FP-C0603-CJ-MFG]
C190  0.1uF_16V_0402  [FP-GRM15-MFG]
C191  0.1uF_16V_0402  [FP-GRM15-MFG]
C192  0.1uF_16V_0402  [FP-GRM15-MFG]
C193  0.1uF_16V_0402  [FP-GRM15-MFG]
C194  0.1uF_16V_0402  [FP-GRM15-MFG]
C195  0.1uF_16V_0402  [FP-GRM15-MFG]
C196  0.1uF_16V_0402  [FP-GRM15-MFG]
C197  0.1uF_16V_0402  [FP-GRM15-MFG]
C198  0.1uF_16V_0402  [FP-GRM15-MFG]
C199  0.1uF_16V_0402  [FP-GRM15-MFG]
C200  0.1uF_16V_0402  [FP-GRM15-MFG]
C201  0.1uF_16V_0402  [FP-GRM15-MFG]
C202  0.1uF_16V_0402  [FP-GRM15-MFG]
C203  0.1uF_16V_0402  [FP-GRM15-MFG]
C204  0.1uF_16V_0402  [FP-GRM15-MFG]
C205  0.1uF_16V_0402  [FP-GRM15-MFG]
C206  0.1uF_16V_0402  [FP-GRM15-MFG]
C207  Capacitance: 22uF  Voltage Rating: 10V  Case Code (Imperial): 0603  [FP-GRM188-0_2-IPC_C]  (hidden comment: GRM188R61A226ME15D)
C208  0.1uF_16V_0402  [FP-GRM15-MFG]
C209  Capacitance: 22uF  Voltage Rating: 10V  Case Code (Imperial): 0603  [FP-GRM188-0_2-IPC_C]  (hidden comment: GRM188R61A226ME15D)
C210  Capacitance: 22uF  Voltage Rating: 10V  Case Code (Imperial): 0603  [FP-GRM188-0_2-IPC_C]  (hidden comment: GRM188R61A226ME15D)
C211  Capacitance: 22uF  Voltage Rating: 10V  Case Code (Imperial): 0603  [FP-GRM188-0_2-IPC_C]  (hidden comment: GRM188R61A226ME15D)
C212  Capacitance: 22uF  Voltage Rating: 10V  Case Code (Imperial): 0603  [FP-GRM188-0_2-IPC_C]  (hidden comment: GRM188R61A226ME15D)
C213  Capacitance: 22uF  Voltage Rating: 10V  Case Code (Imperial): 0603  [FP-GRM188-0_2-IPC_C]  (hidden comment: GRM188R61A226ME15D)
FB4  MPZ2012S601A  [TDK-MPZ2012_V]
J17  L829-1J1T-JM  [BEL_L829-1J1T-JM]
R141  Case/Package: 0402  Resistance: 10kR  Tolerance: 5%  [FP-CRCW0402-e3-IPC_B]  (hidden comment: CRCW040210K0JNED)
R142  Case/Package: 0402  Resistance: 10kR  Tolerance: 5%  [FP-CRCW0402-e3-IPC_B]  (hidden comment: CRCW040210K0JNED)
R143  Case/Package: 0402  Resistance: 10kR  Tolerance: 5%  [FP-CRCW0402-e3-IPC_B]  (hidden comment: CRCW040210K0JNED)
R144  Case/Package: 0402  Resistance: 10kR  Tolerance: 5%  [FP-CRCW0402-e3-IPC_B]  (hidden comment: CRCW040210K0JNED)
R145  Case/Package: 0402  Resistance: 10kR  Tolerance: 5%  [FP-CRCW0402-e3-IPC_B]  (hidden comment: CRCW040210K0JNED)
R146  220_1%_0402  [RESC1005X40X25LL10T10]
R147  DNI_10K  Case/Package: 0402  Resistance: 10kR  Tolerance: 5%  [FP-CRCW0402-e3-IPC_B]  (no BOM)
R148  Case/Package: 0402  Resistance: 10kR  Tolerance: 5%  [FP-CRCW0402-e3-IPC_B]  (hidden comment: CRCW040210K0JNED)
R149  Case/Package: 0402  Resistance: 10kR  Tolerance: 5%  [FP-CRCW0402-e3-IPC_B]  (hidden comment: CRCW040210K0JNED)
R150  220_1%_0402  [RESC1005X40X25LL10T10]
R151  220_1%_0402  [RESC1005X40X25LL10T10]
U23  TPD4EUSB30DQAR  [DQA0010A_V]
U24  TPD4EUSB30DQAR  [DQA0010A_V]

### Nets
CHASSIS_CM4_GND: FB4.2 J17.S1(SHIELD) J17.S2(SHIELD)
GND: C189.1 C190.1 C191.1 C192.1 C193.1 C194.1 C195.1 C196.1 C197.1 C198.1 C199.1 C200.1 C201.1 C202.1 C203.1 C204.1 C205.1 C206.1 C207.2 C208.1 C209.2 C210.2 C211.2 C212.2 C213.2 FB4.1 R147.1 R148.1 R149.1 U23.3(GND) U23.8(GND) U24.3(GND) U24.8(GND)
P0V95_I225: C191.2 C193.2 C195.2 C197.2 C199.2 C201.2 C203.2 C205.2 C207.1 C209.1 C211.1
P3V3: C190.2 C192.2 C194.2 C196.2 C198.2 C200.2 C202.2 C204.2 C206.2 C208.2 C210.1 C212.1 C213.1 J17.14(YA_1) J17.16(CA) R141.2 R142.2 R143.2 R144.2 R145.2
I225_CLKREQ_N: R142.1 ; off-sheet I225_CLKREQ_N
I225_DISABLE_N: R145.1 R147.2 ; off-sheet I225_DISABLE_N
I225_JTAG_CLK: R149.2 ; off-sheet I225_JTAG_CLK
I225_JTAG_RSTN: R148.2 ; off-sheet I225_JTAG_RSTN
I225_LAN_PWR_GOOD: R144.1 ; off-sheet I225_LAN_PWR_GOOD
I225_ULP_WAKE_N: R141.1 ; off-sheet I225_ULP_WAKE_N
I225_WAKE_N: R143.1 ; off-sheet I225_WAKE_N
LED_LINK_ACT#: R150.2 ; off-sheet LED_LINK_ACT#
LED_SPEED_1000#: R146.2 ; off-sheet LED_SPEED_1000#
LED_SPEED_2500#: R151.2 ; off-sheet LED_SPEED_2500#
MDI_A_N: J17.10(TRD1-) U23.4(D2+) U23.7(NC) ; off-sheet MDI_A_N
MDI_A_P: J17.11(TRD1+) U23.5(D2-) U23.6(NC) ; off-sheet MDI_A_P
MDI_B_N: J17.5(TRD2-) U23.1(D1+) U23.10(NC) ; off-sheet MDI_B_N
MDI_B_P: J17.4(TRD2+) U23.2(D1-) U23.9(NC) ; off-sheet MDI_B_P
MDI_C_N: J17.2(TRD3-) U24.4(D2+) U24.7(NC) ; off-sheet MDI_C_N
MDI_C_P: J17.3(TRD3+) U24.5(D2-) U24.6(NC) ; off-sheet MDI_C_P
MDI_D_N: J17.9(TRD4-) U24.1(D1+) U24.10(NC) ; off-sheet MDI_D_N
MDI_D_P: J17.8(TRD4+) U24.2(D1-) U24.9(NC) ; off-sheet MDI_D_P
NetC189_2: C189.2 J17.1(TRCT3) J17.6(TRCT2) J17.7(TRCT4) J17.12(TRCT1)
NetJ17_13: J17.13(YK_1) R146.1
NetJ17_15: J17.15(OK_1) R151.1
NetJ17_17: J17.17(GK_1) R150.1

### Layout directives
differential pair: MDI_A_N, MDI_A_P, MDI_B_N, MDI_B_P, MDI_C_N, MDI_C_P, MDI_D_N, MDI_D_P

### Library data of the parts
C189 = CMP-2006-03300-2: CAP CER 0.1UF 50V X7R 0603; Manufacturer Part Number: C0603X104K5RACTU; Manufacturer: Kemet; Capacitance: 100nF; Material: Ceramic; Tolerance: 10%; Value: 100nF; Temperature Coefficient: 15%
C190-C206 C208 = CMP-2100-03641-2: as C30 on sheet 12-I225_1
C207 C209-C213 = CMP-2000-06337-3: Chip Multilayer Ceramic Capacitors for General Purpose, 0603, 22uF, X5R, 15%, 20%, 10V
FB4 = CMP-2000-05400-1: Chip Bead for Power Line, 600 Ohm, +/- 25%, 2 A, -55 to 125 degC, 2-Pin SMD (0805), RoHS, Tape and Reel; Manufacturer: TDK; Maximum DC Current: 2A; Impedance: 600Ohms; Test Frequency: 100MHz; Case Length: 2mm; Maximum DC Resistance: 100mOhms; Case Height: 0.85mm; Case Width: 1.25mm
J17 = L829-1J1T-JM: MagJack 2.5GBASE-T ¦ 1X1 ¦ OG/Y LED ¦ -40 to 85C ¦ RoHS; MF: Bel Magnetic Solutions
R141-R145 R147-R149 = CMP-2002-08136-3: as R130 on sheet 12-I225_1
R146 R150 R151 = CMP-2002-03891-1: Part Number: RK73H1ETTP2200F; Manufacturer: KOA Speer
U23 U24 = CMP-0326-00027-3: ESD Solution for Super-Speed (6 GBPS) USB 3.0 Interface, 4 Channels, -40 to +85 degC, 10-pin SON (DQA), Green (RoHS & no Sb/Br); Manufacturer: Texas Instruments; Differential Capacitance(pF): 0.05; Serial ATA / eSATA: TRUE; IO Capacitance(Typ)(pF): 0.8; IO Leakage Current(nA): 10; IEC 61000-4-2 Air-Gap(+/- kV): 8

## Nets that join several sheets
GND: 01-CM4_Conn (58 pins), 02-Clocks (16 pins), 03-KSZ9567 (21 pins), 04-Switch_RJ45 (6 pins), 05-Switch_SFP_CM4_RJ45 (40 pins), 06-CM4_USB_HDMI_SDCard (19 pins), 07-KSZ9031_1G_BASET_XCVR (51 pins), 08-Power (51 pins), 09-Switch_Power_Filters (74 pins), 10-RJ45_Protection (20 pins), 12-I225_1 (19 pins), 13-I225_2 (33 pins)
P0V95_I225: 12-I225_1 (7 pins), 13-I225_2 (11 pins)
P1V2: 07-KSZ9031_1G_BASET_XCVR (12 pins), 08-Power (5 pins), 09-Switch_Power_Filters (12 pins)
P2V5: 08-Power (6 pins), 09-Switch_Power_Filters (8 pins)
P3V3: 02-Clocks (10 pins), 03-KSZ9567 (R41.2), 04-Switch_RJ45 (11 pins), 05-Switch_SFP_CM4_RJ45 (15 pins), 06-CM4_USB_HDMI_SDCard (R28.2 U3.5), 07-KSZ9031_1G_BASET_XCVR (11 pins), 08-Power (17 pins), 09-Switch_Power_Filters (C165.1 C166.2 C167.1 R94.1), 11-Switch_Strapping (7 pins), 12-I225_1 (18 pins), 13-I225_2 (20 pins)
P5V: 01-CM4_Conn (6 pins), 06-CM4_USB_HDMI_SDCard (5 pins), 08-Power (25 pins)
SW_AVDDH: 03-KSZ9567 (7 pins), 09-Switch_Power_Filters (12 pins)
SW_AVDDL: 03-KSZ9567 (9 pins), 09-Switch_Power_Filters (14 pins)
SW_DVDDL: 03-KSZ9567 (9 pins), 09-Switch_Power_Filters (14 pins)
SW_VDDHS: 03-KSZ9567 (U1.72 U1.83), 09-Switch_Power_Filters (7 pins)
SW_VDDIO: 03-KSZ9567 (U1.61 U1.68 U1.99), 09-Switch_Power_Filters (8 pins)
SW_VDDLS: 03-KSZ9567 (U1.71 U1.84), 09-Switch_Power_Filters (7 pins)
BRD_RST_N: 01-CM4_Conn (J15.45), 08-Power (R74.2 U9.1)
CM4_GPIO13: 01-CM4_Conn (J15.28), 12-I225_1 (U20.8)
CM4_GPIO19: 01-CM4_Conn (J15.26), 12-I225_1 (U20.4)
CM4_GPIO20: 01-CM4_Conn (J15.27), 12-I225_1 (R111.1 U20.15)
CM4_GPIO21: 01-CM4_Conn (J15.25), 12-I225_1 (U20.11)
CM4_GPIO26: 01-CM4_Conn (J15.24), 12-I225_1 (U20.1)
ETH_PAIR0_N: 01-CM4_Conn (J15.10), 07-KSZ9031_1G_BASET_XCVR (U2.2 U2.9 U4.3)
ETH_PAIR0_P: 01-CM4_Conn (J15.12), 07-KSZ9031_1G_BASET_XCVR (U2.1 U2.10 U4.2)
ETH_PAIR1_N: 01-CM4_Conn (J15.6), 07-KSZ9031_1G_BASET_XCVR (U2.4 U2.7 U4.6)
ETH_PAIR1_P: 01-CM4_Conn (J15.4), 07-KSZ9031_1G_BASET_XCVR (U2.5 U2.6 U4.5)
ETH_PAIR2_N: 01-CM4_Conn (J15.9), 07-KSZ9031_1G_BASET_XCVR (U4.8 U5.2 U5.9)
ETH_PAIR2_P: 01-CM4_Conn (J15.11), 07-KSZ9031_1G_BASET_XCVR (U4.7 U5.1 U5.10)
ETH_PAIR3_N: 01-CM4_Conn (J15.5), 07-KSZ9031_1G_BASET_XCVR (U4.11 U5.4 U5.7)
ETH_PAIR3_P: 01-CM4_Conn (J15.3), 07-KSZ9031_1G_BASET_XCVR (U4.10 U5.5 U5.6)
HDMI0_CEC: 01-CM4_Conn (J14.51), 06-CM4_USB_HDMI_SDCard (J7.13)
HDMI0_CLK_N: 01-CM4_Conn (J14.90), 06-CM4_USB_HDMI_SDCard (L7.2)
HDMI0_CLK_P: 01-CM4_Conn (J14.88), 06-CM4_USB_HDMI_SDCard (L7.3)
HDMI0_HP: 01-CM4_Conn (J14.53), 06-CM4_USB_HDMI_SDCard (J7.19)
HDMI0_SCL: 01-CM4_Conn (J14.100), 06-CM4_USB_HDMI_SDCard (J7.15)
HDMI0_SDA: 01-CM4_Conn (J14.99), 06-CM4_USB_HDMI_SDCard (J7.16)
HDMI0_TX0_N: 01-CM4_Conn (J14.84), 06-CM4_USB_HDMI_SDCard (L6.2)
HDMI0_TX0_P: 01-CM4_Conn (J14.82), 06-CM4_USB_HDMI_SDCard (L6.3)
HDMI0_TX1_N: 01-CM4_Conn (J14.78), 06-CM4_USB_HDMI_SDCard (L5.2)
HDMI0_TX1_P: 01-CM4_Conn (J14.76), 06-CM4_USB_HDMI_SDCard (L5.3)
HDMI0_TX2_N: 01-CM4_Conn (J14.72), 06-CM4_USB_HDMI_SDCard (L4.2)
HDMI0_TX2_P: 01-CM4_Conn (J14.70), 06-CM4_USB_HDMI_SDCard (L4.3)
I225_CLKREQ_N: 12-I225_1 (U18.3), 13-I225_2 (R142.1)
I225_DISABLE_N: 12-I225_1 (U18.2), 13-I225_2 (R145.1 R147.2)
I225_JTAG_CLK: 12-I225_1 (U18.29), 13-I225_2 (R149.2)
I225_JTAG_RSTN: 12-I225_1 (U18.16), 13-I225_2 (R148.2)
I225_LAN_PWR_GOOD: 12-I225_1 (U18.1), 13-I225_2 (R144.1)
I225_ULP_WAKE_N: 12-I225_1 (U18.4), 13-I225_2 (R141.1)
I225_WAKE_N: 12-I225_1 (U18.12), 13-I225_2 (R143.1)
LED_LINK_ACT#: 12-I225_1 (U18.30), 13-I225_2 (R150.2)
LED_SPEED_1000#: 12-I225_1 (U18.32), 13-I225_2 (R146.2)
LED_SPEED_2500#: 12-I225_1 (U18.31), 13-I225_2 (R151.2)
MDI_A_N: 12-I225_1 (U18.46), 13-I225_2 (J17.10 U23.4 U23.7)
MDI_A_P: 12-I225_1 (U18.45), 13-I225_2 (J17.11 U23.5 U23.6)
MDI_B_N: 12-I225_1 (U18.49), 13-I225_2 (J17.5 U23.1 U23.10)
MDI_B_P: 12-I225_1 (U18.48), 13-I225_2 (J17.4 U23.2 U23.9)
MDI_C_N: 12-I225_1 (U18.52), 13-I225_2 (J17.2 U24.4 U24.7)
MDI_C_P: 12-I225_1 (U18.51), 13-I225_2 (J17.3 U24.5 U24.6)
MDI_D_N: 12-I225_1 (U18.55), 13-I225_2 (J17.9 U24.1 U24.10)
MDI_D_P: 12-I225_1 (U18.54), 13-I225_2 (J17.8 U24.2 U24.9)
P1_LED0: 03-KSZ9567 (R31.2), 04-Switch_RJ45 (J1.27)
P1_LED1: 03-KSZ9567 (R32.2), 04-Switch_RJ45 (J1.30), 11-Switch_Strapping (R97.1)
P1_TXRXA_N: 03-KSZ9567 (U1.2), 04-Switch_RJ45 (J1.21), 10-RJ45_Protection (U10.2 U10.9)
P1_TXRXA_P: 03-KSZ9567 (U1.1), 04-Switch_RJ45 (J1.15), 10-RJ45_Protection (U10.1 U10.10)
P1_TXRXB_N: 03-KSZ9567 (U1.5), 04-Switch_RJ45 (J1.16), 10-RJ45_Protection (U10.5 U10.6)
P1_TXRXB_P: 03-KSZ9567 (U1.4), 04-Switch_RJ45 (J1.23), 10-RJ45_Protection (U10.4 U10.7)
P1_TXRXC_N: 03-KSZ9567 (U1.7), 04-Switch_RJ45 (J1.24), 10-RJ45_Protection (U12.2 U12.9)
P1_TXRXC_P: 03-KSZ9567 (U1.6), 04-Switch_RJ45 (J1.18), 10-RJ45_Protection (U12.1 U12.10)
P1_TXRXD_N: 03-KSZ9567 (U1.9), 04-Switch_RJ45 (J1.19), 10-RJ45_Protection (U12.5 U12.6)
P1_TXRXD_P: 03-KSZ9567 (U1.8), 04-Switch_RJ45 (J1.26), 10-RJ45_Protection (U12.4 U12.7)
P2_LED0: 03-KSZ9567 (R33.2), 04-Switch_RJ45 (J2.31), 11-Switch_Strapping (R100.1)
P2_LED1: 03-KSZ9567 (R34.2), 04-Switch_RJ45 (J2.34), 11-Switch_Strapping (R98.1)
P2_TXRXA_N: 03-KSZ9567 (U1.13), 04-Switch_RJ45 (J2.13), 10-RJ45_Protection (U11.2 U11.9)
P2_TXRXA_P: 03-KSZ9567 (U1.12), 04-Switch_RJ45 (J2.6), 10-RJ45_Protection (U11.1 U11.10)
P2_TXRXB_N: 03-KSZ9567 (U1.16), 04-Switch_RJ45 (J2.5), 10-RJ45_Protection (U11.5 U11.6)
P2_TXRXB_P: 03-KSZ9567 (U1.15), 04-Switch_RJ45 (J2.11), 10-RJ45_Protection (U11.4 U11.7)
P2_TXRXC_N: 03-KSZ9567 (U1.18), 04-Switch_RJ45 (J2.10), 10-RJ45_Protection (U13.2 U13.9)
P2_TXRXC_P: 03-KSZ9567 (U1.17), 04-Switch_RJ45 (J2.3), 10-RJ45_Protection (U13.1 U13.10)
P2_TXRXD_N: 03-KSZ9567 (U1.21), 04-Switch_RJ45 (J2.2), 10-RJ45_Protection (U13.5 U13.6)
P2_TXRXD_P: 03-KSZ9567 (U1.20), 04-Switch_RJ45 (J2.8), 10-RJ45_Protection (U13.4 U13.7)
P3_LED0: 03-KSZ9567 (R35.2), 04-Switch_RJ45 (J2.27)
P3_LED1: 03-KSZ9567 (R36.2), 04-Switch_RJ45 (J2.30), 11-Switch_Strapping (R102.1)
P3_TXRXA_N: 03-KSZ9567 (U1.25), 04-Switch_RJ45 (J2.21), 10-RJ45_Protection (U15.2 U15.9)
P3_TXRXA_P: 03-KSZ9567 (U1.24), 04-Switch_RJ45 (J2.15), 10-RJ45_Protection (U15.1 U15.10)
P3_TXRXB_N: 03-KSZ9567 (U1.27), 04-Switch_RJ45 (J2.16), 10-RJ45_Protection (U15.5 U15.6)
P3_TXRXB_P: 03-KSZ9567 (U1.26), 04-Switch_RJ45 (J2.23), 10-RJ45_Protection (U15.4 U15.7)
P3_TXRXC_N: 03-KSZ9567 (U1.29), 04-Switch_RJ45 (J2.24), 10-RJ45_Protection (U17.2 U17.9)
P3_TXRXC_P: 03-KSZ9567 (U1.28), 04-Switch_RJ45 (J2.18), 10-RJ45_Protection (U17.1 U17.10)
P3_TXRXD_N: 03-KSZ9567 (U1.32), 04-Switch_RJ45 (J2.19), 10-RJ45_Protection (U17.5 U17.6)
P3_TXRXD_P: 03-KSZ9567 (U1.31), 04-Switch_RJ45 (J2.26), 10-RJ45_Protection (U17.4 U17.7)
P4_LED0: 03-KSZ9567 (R37.2), 04-Switch_RJ45 (R53.2), 11-Switch_Strapping (R99.1)
P4_LED1: 03-KSZ9567 (R38.2), 04-Switch_RJ45 (R54.2), 11-Switch_Strapping (R101.1)
P4_TXRXA_N: 03-KSZ9567 (U1.35), 04-Switch_RJ45 (J3.10), 10-RJ45_Protection (U14.2 U14.9)
P4_TXRXA_P: 03-KSZ9567 (U1.34), 04-Switch_RJ45 (J3.11), 10-RJ45_Protection (U14.1 U14.10)
P4_TXRXB_N: 03-KSZ9567 (U1.38), 04-Switch_RJ45 (J3.5), 10-RJ45_Protection (U14.5 U14.6)
P4_TXRXB_P: 03-KSZ9567 (U1.37), 04-Switch_RJ45 (J3.4), 10-RJ45_Protection (U14.4 U14.7)
P4_TXRXC_N: 03-KSZ9567 (U1.40), 04-Switch_RJ45 (J3.2), 10-RJ45_Protection (U16.2 U16.9)
P4_TXRXC_P: 03-KSZ9567 (U1.39), 04-Switch_RJ45 (J3.3), 10-RJ45_Protection (U16.1 U16.10)
P4_TXRXD_N: 03-KSZ9567 (U1.43), 04-Switch_RJ45 (J3.9), 10-RJ45_Protection (U16.5 U16.6)
P4_TXRXD_P: 03-KSZ9567 (U1.42), 04-Switch_RJ45 (J3.8), 10-RJ45_Protection (U16.4 U16.7)
P5_LED0: 03-KSZ9567 (R39.2), 04-Switch_RJ45 (J1.31)
P5_LED1: 03-KSZ9567 (R40.2), 04-Switch_RJ45 (J1.34), 11-Switch_Strapping (R103.1)
P5_TXRXA_N: 03-KSZ9567 (U1.113), 04-Switch_RJ45 (J1.13), 10-RJ45_Protection (U19.2 U19.9)
P5_TXRXA_P: 03-KSZ9567 (U1.112), 04-Switch_RJ45 (J1.6), 10-RJ45_Protection (U19.1 U19.10)
P5_TXRXB_N: 03-KSZ9567 (U1.116), 04-Switch_RJ45 (J1.5), 10-RJ45_Protection (U19.5 U19.6)
P5_TXRXB_P: 03-KSZ9567 (U1.115), 04-Switch_RJ45 (J1.11), 10-RJ45_Protection (U19.4 U19.7)
P5_TXRXC_N: 03-KSZ9567 (U1.118), 04-Switch_RJ45 (J1.10), 10-RJ45_Protection (U21.2 U21.9)
P5_TXRXC_P: 03-KSZ9567 (U1.117), 04-Switch_RJ45 (J1.3), 10-RJ45_Protection (U21.1 U21.10)
P5_TXRXD_N: 03-KSZ9567 (U1.121), 04-Switch_RJ45 (J1.2), 10-RJ45_Protection (U21.5 U21.6)
P5_TXRXD_P: 03-KSZ9567 (U1.120), 04-Switch_RJ45 (J1.8), 10-RJ45_Protection (U21.4 U21.7)
P6_RGMII_RXCLK: 03-KSZ9567 (U1.57), 07-KSZ9031_1G_BASET_XCVR (R14.1)
P6_RGMII_RXCTL: 03-KSZ9567 (U1.58), 07-KSZ9031_1G_BASET_XCVR (R15.1)
P6_RGMII_RXD0: 03-KSZ9567 (R13.2 U1.65), 07-KSZ9031_1G_BASET_XCVR (R16.1)
P6_RGMII_RXD1: 03-KSZ9567 (R12.2 U1.64), 07-KSZ9031_1G_BASET_XCVR (R17.1)
P6_RGMII_RXD2: 03-KSZ9567 (R11.2 U1.63), 07-KSZ9031_1G_BASET_XCVR (R18.1)
P6_RGMII_RXD3: 03-KSZ9567 (R10.2 U1.62), 07-KSZ9031_1G_BASET_XCVR (R19.1)
P6_RGMII_TXCLK: 03-KSZ9567 (U1.48), 07-KSZ9031_1G_BASET_XCVR (R20.1)
P6_RGMII_TXCTL: 03-KSZ9567 (U1.49), 07-KSZ9031_1G_BASET_XCVR (R21.1)
P6_RGMII_TXD0: 03-KSZ9567 (U1.55), 07-KSZ9031_1G_BASET_XCVR (R22.1)
P6_RGMII_TXD1: 03-KSZ9567 (U1.54), 07-KSZ9031_1G_BASET_XCVR (R23.1)
P6_RGMII_TXD2: 03-KSZ9567 (U1.53), 07-KSZ9031_1G_BASET_XCVR (R24.1)
P6_RGMII_TXD3: 03-KSZ9567 (U1.52), 07-KSZ9031_1G_BASET_XCVR (R25.1)
PCIE_CLK_N: 01-CM4_Conn (J14.12), 12-I225_1 (R118.1)
PCIE_CLK_P: 01-CM4_Conn (J14.10), 12-I225_1 (R117.1)
PCIE_PERST_N: 01-CM4_Conn (J14.9), 12-I225_1 (R119.1 U18.13)
PCIE_RX_N: 01-CM4_Conn (J14.18), 12-I225_1 (C184.1)
PCIE_RX_P: 01-CM4_Conn (J14.16), 12-I225_1 (C32.1)
PCIE_TX_N: 01-CM4_Conn (J14.24), 12-I225_1 (R116.1)
PCIE_TX_P: 01-CM4_Conn (J14.22), 12-I225_1 (R115.1)
PHY_25MHz: 02-Clocks (C175.2), 07-KSZ9031_1G_BASET_XCVR (U4.46)
PHY_INT_N: 01-CM4_Conn (J15.47), 07-KSZ9031_1G_BASET_XCVR (R87.2)
PHY_MDC: 01-CM4_Conn (J15.54), 07-KSZ9031_1G_BASET_XCVR (R84.1)
PHY_MDIO: 01-CM4_Conn (J15.50), 07-KSZ9031_1G_BASET_XCVR (R86.1)
PHY_RST_N: 07-KSZ9031_1G_BASET_XCVR (R83.2), 08-Power (R81.1)
SD_CLK: 01-CM4_Conn (J15.57), 06-CM4_USB_HDMI_SDCard (SD1.5)
SD_CMD: 01-CM4_Conn (J15.62), 06-CM4_USB_HDMI_SDCard (SD1.3)
SD_DAT0: 01-CM4_Conn (J15.63), 06-CM4_USB_HDMI_SDCard (SD1.7)
SD_DAT1: 01-CM4_Conn (J15.67), 06-CM4_USB_HDMI_SDCard (SD1.8)
SD_DAT2: 01-CM4_Conn (J15.69), 06-CM4_USB_HDMI_SDCard (SD1.1)
SD_DAT3: 01-CM4_Conn (J15.61), 06-CM4_USB_HDMI_SDCard (SD1.2)
SD_PWR_ON: 01-CM4_Conn (J15.75), 06-CM4_USB_HDMI_SDCard (R28.1 U3.4)
SFP1_SCL: 01-CM4_Conn (J15.56), 05-Switch_SFP_CM4_RJ45 (J4.5 R4.2)
SFP1_SDA: 01-CM4_Conn (J15.58), 05-Switch_SFP_CM4_RJ45 (J4.4 R3.2)
SFP_SW_N: 03-KSZ9567 (U1.78), 05-Switch_SFP_CM4_RJ45 (J4.12)
SFP_SW_P: 03-KSZ9567 (U1.79), 05-Switch_SFP_CM4_RJ45 (J4.13)
SPI0_CE0: 01-CM4_Conn (J15.39), 03-KSZ9567 (R44.2)
SPI0_CLK: 01-CM4_Conn (J15.38), 03-KSZ9567 (R45.1)
SPI0_MISO: 01-CM4_Conn (J15.40), 03-KSZ9567 (R47.1)
SPI0_MOSI: 01-CM4_Conn (J15.44), 03-KSZ9567 (R46.1)
SW_25MHz: 02-Clocks (C174.2), 03-KSZ9567 (U1.126)
SW_INTR_N: 01-CM4_Conn (J15.41), 03-KSZ9567 (R41.1 U1.94)
SW_RST_N: 03-KSZ9567 (R43.2), 08-Power (R75.1)
SW_SFP_N: 03-KSZ9567 (U1.82), 05-Switch_SFP_CM4_RJ45 (J4.19)
SW_SFP_P: 03-KSZ9567 (U1.81), 05-Switch_SFP_CM4_RJ45 (J4.18)
USB_N: 01-CM4_Conn (J14.3), 06-CM4_USB_HDMI_SDCard (L3.2)
USB_P: 01-CM4_Conn (J14.5), 06-CM4_USB_HDMI_SDCard (L3.3)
